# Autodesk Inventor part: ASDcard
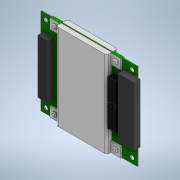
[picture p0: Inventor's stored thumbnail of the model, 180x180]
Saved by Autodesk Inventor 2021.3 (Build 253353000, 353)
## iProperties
Created: 2021-12
Part Number: ASDcard
Material: 一般
Document SubType Name: Modeling
Designer: kengo
Density: 1 g/cm^3
Appearance: 既定
Author: kengo
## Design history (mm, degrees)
sketch "スケッチ1"
  geometry: L1 (-51.084, 27.157)-(43.916, 27.157); L2 (43.916, 27.157)-(43.916, -57.843); L3 (43.916, -57.843)-(-51.084, -57.843); L4 (-51.084, -57.843)-(-51.084, 27.157); 1 further point
  constraints: 8 end point, 2 parallel, 1 horizontal, 1 perpendicular
  dimensions: "d0" = 95 distance of L1.start L1.end; "d1" = 85 distance of L1.end L2.end
extrude "押し出し1" new body sketch "スケッチ1" distance "d2" = 1; taper "d3" = 0 deg
sketch "スケッチ2"
  geometry: L1 (-31.084, 27.057)-(18.916, 27.057); L2 (18.916, 27.057)-(18.916, -57.743); L3 (18.916, -57.743)-(-31.084, -57.743); L4 (-31.084, -57.743)-(-31.084, 27.057); L5 (-51.084, 27.157)-(-51.084, -57.843) reference; L6 (43.916, 27.157)-(-51.084, 27.157) reference; L7 (-51.084, -57.843)-(43.916, -57.843) reference; 1 further point
  constraints: 8 end point, 2 parallel, 1 horizontal, 1 perpendicular
  dimensions: "d4" = 20 distance between parallel lines of L5 L4; "d5" = 50 distance between parallel lines of L2 L4; "d6" = 0.1 distance between parallel lines of L1 L6; "d7" = 0.1 distance between parallel lines of L7 L3
extrude "押し出し2" join sketch "スケッチ2" distance "d8" = 5; taper "d10" = 0 deg; dims "d9" = 6, "d11" = 0
sketch "スケッチ3"
  geometry: L1 (43.916, 27.157)-(-51.084, 27.157) reference; L2 (-31.084, 27.057)-(-31.084, -57.743) reference; L3 (-41.084, 27.157)-(-31.084, 27.157); L4 (-31.084, 27.157)-(-31.084, 17.157); L5 (-31.084, 17.157)-(-41.084, 17.157); L6 (-41.084, 17.157)-(-41.084, 27.157); L7 (-41.084, -47.843)-(-31.084, -47.843); L8 (-31.084, -47.843)-(-31.084, -57.843); L9 (-31.084, -57.843)-(-41.084, -57.843); L10 (-41.084, -57.843)-(-41.084, -47.843); L11 (18.916, 27.157)-(28.916, 27.157); L12 (28.916, 27.157)-(28.916, 17.157); L13 (28.916, 17.157)-(18.916, 17.157); L14 (18.916, 17.157)-(18.916, 27.157); L15 (18.916, -47.843)-(28.916, -47.843); L16 (28.916, -47.843)-(28.916, -57.843); L17 (28.916, -57.843)-(18.916, -57.843); L18 (18.916, -57.843)-(18.916, -47.843); 7 further points
  constraints: 32 end point, 2 horizontal, 2 parallel, 2 point on line, 1 perpendicular, 1 vertical, 24 other
  dimensions: "d12" = 10 distance of L5.end L3.start; "d13" = 10 distance between parallel lines of L2 L6; "d16" = 75 distance of L3.start L7.start; "d19" = 60 distance of L3.start L11.start
extrude "押し出し3" join sketch "スケッチ3" distance "d22" = 1; taper "d24" = 0 deg; dims "d23" = 2, "d25" = 0
sketch "スケッチ4"
  geometry: L1 (-48.084, 11.157)-(-38.084, 11.157); L2 (-38.084, 11.157)-(-38.084, -41.843); L3 (-38.084, -41.843)-(-48.084, -41.843); L4 (-48.084, -41.843)-(-48.084, 11.157); L5 (-51.084, 27.157)-(-51.084, -57.843) reference; L6 (-41.084, 27.157)-(-51.084, 27.157) reference; 1 further point
  constraints: 8 end point, 2 parallel, 1 horizontal, 1 perpendicular
  dimensions: "d26" = 10 distance of L2.end L3.end; "d27" = 3 distance between parallel lines of L5 L4; "d28" = 53 distance of L1.end L2.end; "d29" = 16 distance between parallel lines of L6 L1
extrude "押し出し4" join sketch "スケッチ4" distance "d30" = 6; taper "d31" = 0 deg
sketch "スケッチ5"
  geometry: L1 (30.916, 18.157)-(46.916, 18.157); L2 (46.916, 18.157)-(46.916, -39.843); L3 (46.916, -39.843)-(30.916, -39.843); L4 (30.916, -39.843)-(30.916, 18.157); L5 (18.916, -57.743)-(18.916, 27.057) reference; L6 (43.916, 27.157)-(28.916, 27.157) reference; 1 further point
  constraints: 8 end point, 2 parallel, 1 horizontal, 1 perpendicular
  dimensions: "d32" = 58 distance of L1.end L2.end; "d33" = 12 distance between parallel lines of L5 L4; "d34" = 9 distance between parallel lines of L6 L1; "d35" = 16 distance of L2.end L3.end
extrude "押し出し5" join sketch "スケッチ5" distance "d36" = 6; taper "d37" = 0 deg
fillet "フィレット1" dims "d38" = 2
sketch "スケッチ6"
  geometry: L1 (20.916, 11.157)-(22.916, 11.157); L2 (22.916, 11.157)-(22.916, -10.843); L3 (22.916, -10.843)-(20.916, -10.843); L4 (20.916, -10.843)-(20.916, 11.157); L5 (18.916, -57.743)-(18.916, 27.057) reference; L6 (18.916, 17.157)-(28.916, 17.157) reference; L7 (24.116, 11.157)-(26.116, 11.157); L8 (26.116, 11.157)-(26.116, -10.843); L9 (26.116, -10.843)-(24.116, -10.843); L10 (24.116, -10.843)-(24.116, 11.157); L11 (27.316, 11.157)-(29.316, 11.157); L12 (29.316, 11.157)-(29.316, -10.843); L13 (29.316, -10.843)-(27.316, -10.843); L14 (27.316, -10.843)-(27.316, 11.157); L15 (20.916, -11.843)-(22.916, -11.843); L16 (22.916, -11.843)-(22.916, -33.843); L17 (22.916, -33.843)-(20.916, -33.843); L18 (20.916, -33.843)-(20.916, -11.843); L19 (24.116, -11.843)-(26.116, -11.843); L20 (26.116, -11.843)-(26.116, -33.843); L21 (26.116, -33.843)-(24.116, -33.843); L22 (24.116, -33.843)-(24.116, -11.843); L23 (27.316, -11.843)-(29.316, -11.843); L24 (29.316, -11.843)-(29.316, -33.843); L25 (29.316, -33.843)-(27.316, -33.843); L26 (27.316, -33.843)-(27.316, -11.843); 1 further point
  constraints: 48 end point, 2 horizontal, 2 parallel, 1 perpendicular, 1 vertical, 40 other
  dimensions: "d39" = 22 distance of L1.end L2.end; "d40" = 2 distance between parallel lines of L5 L4; "d41" = 2 distance between parallel lines of L2 L4; "d42" = 6 distance between parallel lines of L6 L1; "d45" = 3.2 distance of L1.start L7.start; "d48" = 23 distance of L1.start L15.start
extrude "押し出し6" join sketch "スケッチ6" distance "d51" = 7; taper "d52" = 0 deg
fillet "フィレット2" dims "d53" = 0.7
sketch "スケッチ7"
  geometry: L1 (-51.084, 27.157)-(-51.084, -57.843) reference; L2 (-51.084, -57.843)-(-41.084, -57.843) reference; 5 further points
  constraints: 1 horizontal, 1 vertical, 3 other
  dimensions: "d54" = 5 distance from line of L1 point (-46.084, -52.843); "d55" = 5 distance from line of L2 point (-46.084, -52.843); "d58" = 85 distance of point (-46.084, -52.843) point (38.916, -52.843); "d61" = 75 distance of point (-46.084, -52.843) point (-46.084, 22.157)
hole "穴1" sketch "スケッチ7" at (-46.084, -52.843), (38.916, -52.843), (-46.084, 22.157), (38.916, 22.157) diameter "d64" = 4; stored, may be unused: countersink angle "d68" = 90 deg, drill point angle "d70" = 118 deg; dims "d65" = 6, "d66" = 4, "d67" = 2, "d69" = 100
sketch "スケッチ8"
  geometry: L1 (28.916, 17.157)-(28.916, 27.157) reference; L2 (28.916, 27.157)-(18.916, 27.157) reference; C1 r 2.5 at (23.916, 22.157); C2 r 2.5 at (23.916, -52.843); C3 r 2.5 at (-36.084, 22.157); C4 r 2.5 at (-36.084, -52.843); 1 further point
  constraints: 4 centre point, 1 horizontal, 1 vertical, 6 other
  dimensions: "d71" = 5 distance from line of L1 C1.centre; "d72" = 5 distance from line of C1.centre L2; "d73" = 5 diameter of C1; "d76" = 75 distance of C1.centre C2.centre; "d79" = 60 distance of C1.centre C3.centre
extrude "押し出し7" join sketch "スケッチ8" distance "d82" = 1.5; taper "d84" = 0 deg; dims "d83" = 4.5, "d85" = 0
fillet "フィレット3" dims "d86" = 1
node "ソリッド1"
